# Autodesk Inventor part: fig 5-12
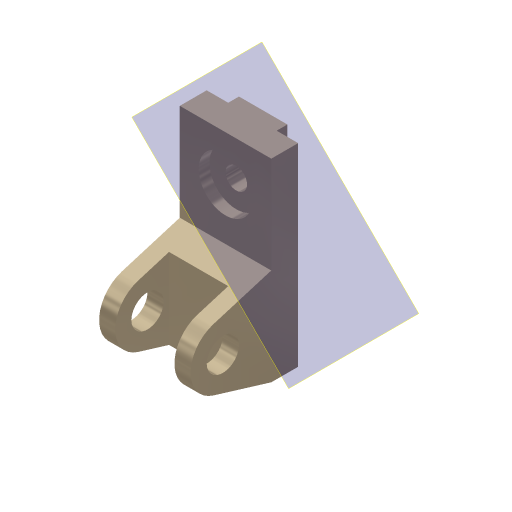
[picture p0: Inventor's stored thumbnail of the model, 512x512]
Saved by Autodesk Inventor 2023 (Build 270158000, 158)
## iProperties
Created: 2001-11
Part Number: fig 5-12
Document SubType Name: Modeling
Designer: Renu Muthoo
Density: 1 g/cm^3
Material: Generic
Appearance: Metal-Titanium (Polished)
Control State: 0
Master: False
Checked Out: False
Shininess: 65.0
Angle Display Precision: 2
Document Length Units: 11269
Document Angle Units: 11279
Document Time Units: 11290
Document Mass Units: 11283
Document Length Units Precision: 3
Document Angle Units Precision: 2
Compacted: False
Density: 0.0
Volumn: 0.0
Area: 0.0
PropertySet Name: Model Information
Author: Renu Muthoo
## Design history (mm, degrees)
node "Sketch1"
sketch "Sketch2"
  geometry: L1 (33.257, 104.664)-(33.257, -75.336); L2 (33.257, -75.336)-(8.257, -75.336); L3 (8.257, -75.336)-(-45.451, -59.045); L4 (-45.451, -1.628)-(8.257, 14.664); L5 (8.257, 14.664)-(8.257, 104.664); L6 (8.257, 104.664)-(33.257, 104.664); C1 r 15 at (-36.743, -30.336); A1 r 30 centre (-36.743, -30.336) between (-45.451, -1.628) and (-45.451, -59.045)
  constraints: 12 end point, 2 centre point, 2 equal length, 2 parallel, 2 point on circle, 2 tangent, 1 coincident, 1 perpendicular, 1 vertical
  dimensions: "d0" = 180 distance of L1.start L1.end; "d1" = 30 radius of A1; "d2" = 25 distance of L5.end L1.start; "d3" = 45 distance from line of L2 A1.centre; "d4" = 70 distance from line of L1 A1.centre; "d5" = 30 diameter of C1
extrude "Extrusion1" new body sketch "Sketch2" distance "d6" = 85; taper "d7" = 0 deg
workplane "Work Plane1"
sketch "Sketch3"
  geometry: L1 (15, 62.364)-(70, 62.364); L2 (70, 62.364)-(70, -52.386); L3 (70, -52.386)-(15, -52.386); L4 (15, -52.386)-(15, 62.364); L5 (0, -45)-(0, -28.708) reference
  constraints: 8 end point, 2 parallel, 1 horizontal, 1 perpendicular
  dimensions: "d8" = 55 distance of L1.start L1.end; "d9" = 15 distance between parallel lines of L5 L4
extrude "Extrusion2" cut sketch "Sketch3" distance "d10" = 50; taper "d11" = 0 deg
sketch "Sketch4"
  geometry: L1 (0, 25)-(85, 25) reference; L2 (0, 0)-(0, 25) reference; L3 (20, 25)-(65, 25); L4 (65, 25)-(65, 35); L5 (65, 35)-(20, 35); L6 (20, 35)-(20, 25)
  constraints: 8 end point, 2 parallel, 1 horizontal, 1 perpendicular, 1 point on line
  dimensions: "d12" = 45 distance of L4.end L5.end; "d13" = 10 distance of L3.end L4.end; "d14" = 20 distance between parallel lines of L2 L6
extrude "Extrusion3" join sketch "Sketch4" stored distance "d15" = 50; taper "d16" = 0 deg
sketch "Sketch5"
  geometry: L1 (85, 0)-(85, 90) reference; L2 (0, 90)-(85, 90) reference; 1 further point
  dimensions: "d17" = 42 distance from line of L2 point (42.5, 48); "d18" = 42.5 distance from line of L1 point (42.5, 48)
hole "Hole1" sketch "Sketch5" at (42.5, 48) diameter "d19" = 20; stored, may be unused: countersink angle "d23" = 82 deg, drill point angle "d25" = 118 deg; dims "d20" = 6, "d21" = 50, "d22" = 10, "d24" = 8
workplane "Work Plane8"
body "Solid1"
other parameters: "d28" = 135 deg
